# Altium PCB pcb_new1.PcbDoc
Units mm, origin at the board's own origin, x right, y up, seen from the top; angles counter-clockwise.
Board outline 81.51 x 54.69 mm, 2 copper layers (Top Layer, Bottom Layer); 60 components, 48 nets, 246 pads, 37 vias.
Unrouted connection lines stored in the file: 3.
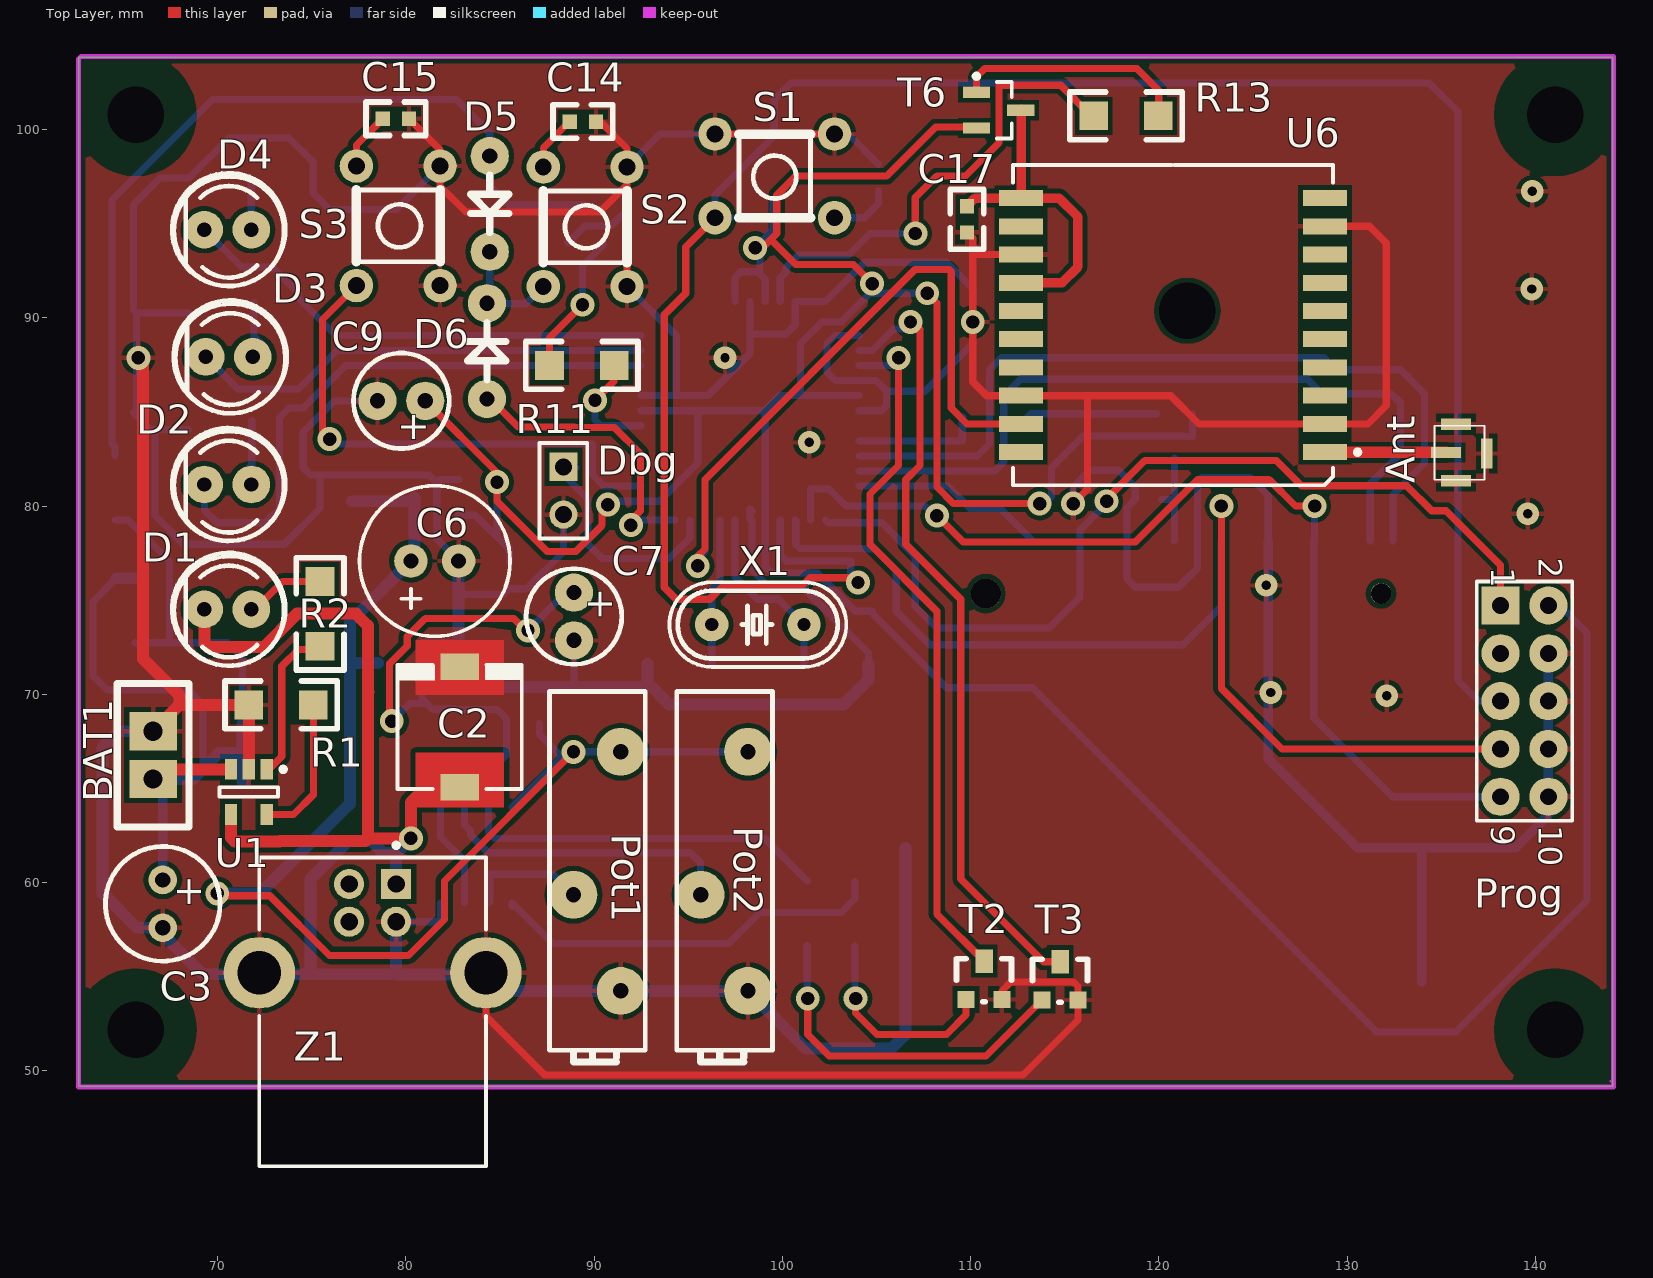
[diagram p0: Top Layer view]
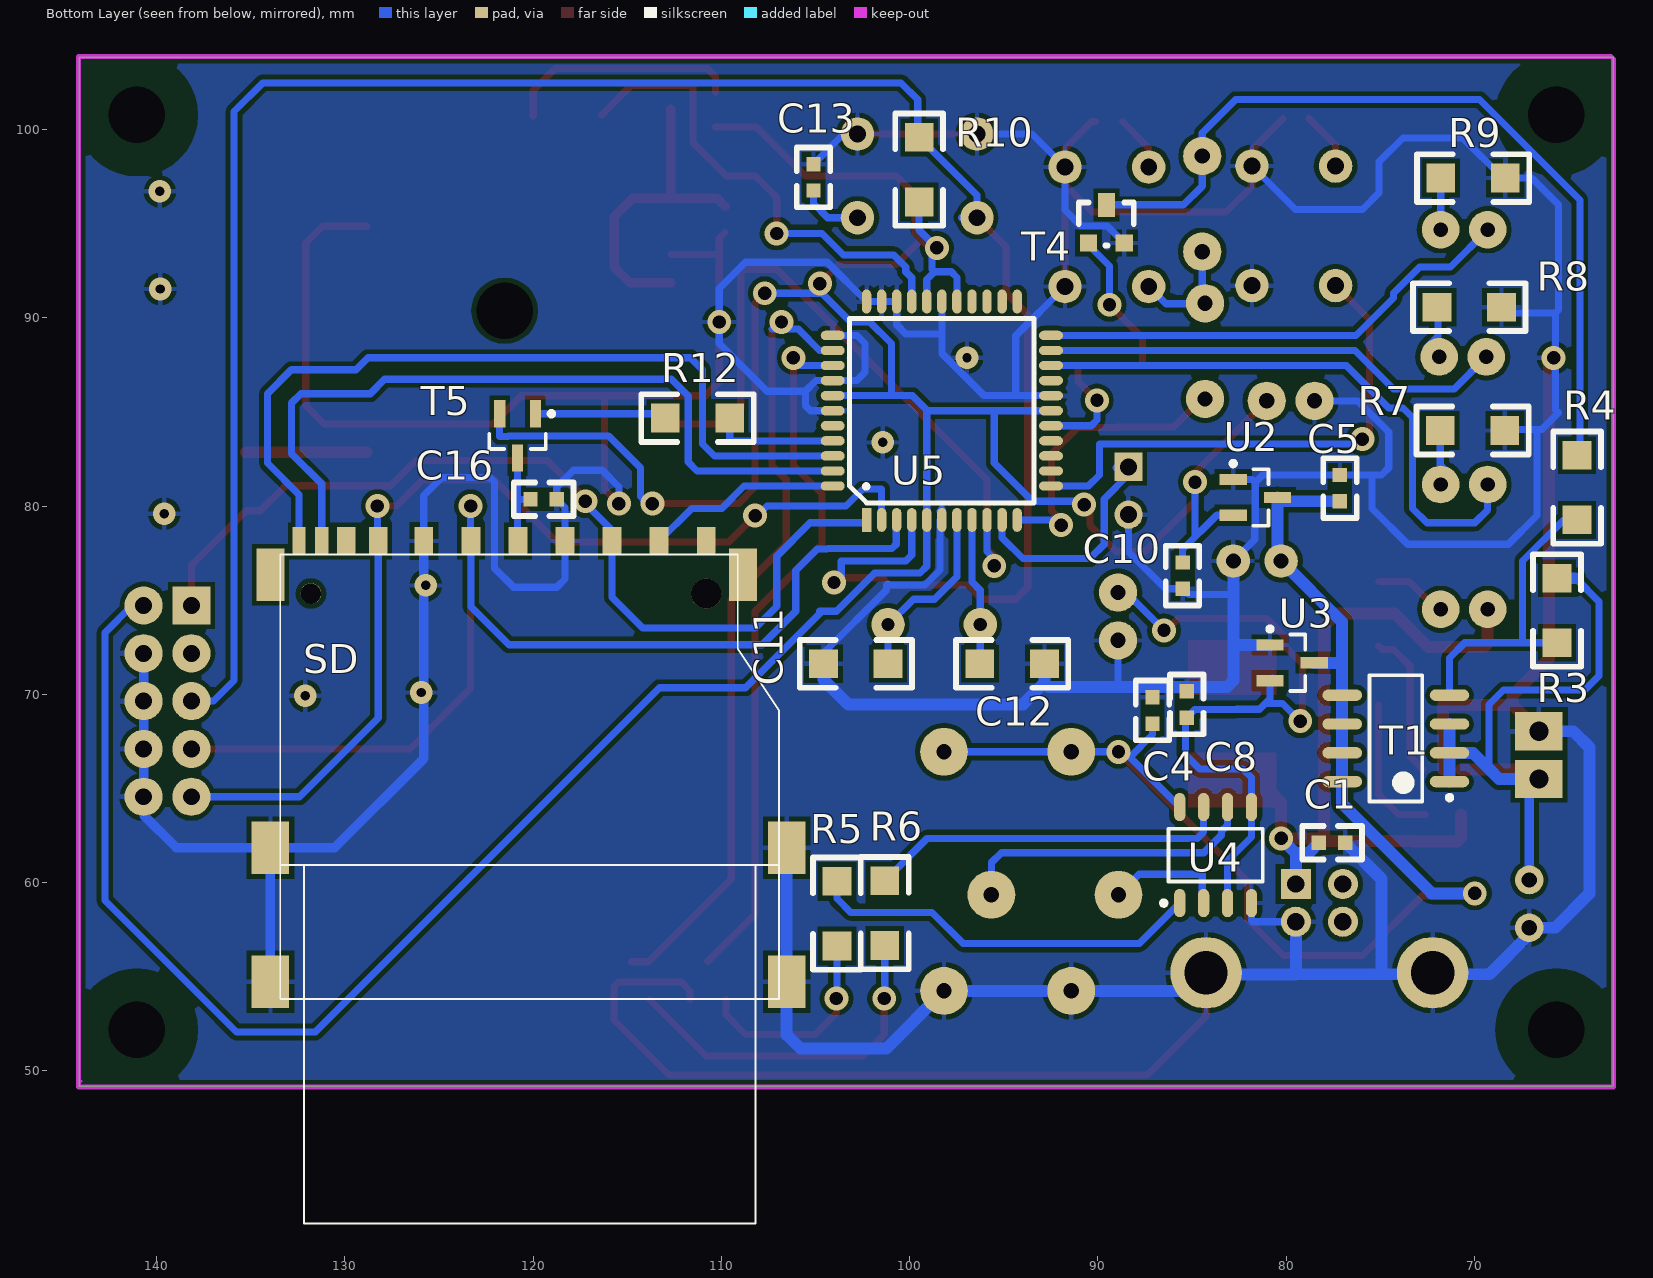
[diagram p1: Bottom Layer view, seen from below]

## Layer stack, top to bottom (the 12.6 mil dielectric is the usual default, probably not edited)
Top Layer: signal copper 0.0356
Dielectric: core 0.32, FR-4, Dk 4.8
Bottom Layer: signal copper 0.0356

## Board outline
62.611,103.861 62.611,49.174 144.12,49.174 144.12,103.861

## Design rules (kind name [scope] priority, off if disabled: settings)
Clearance [All] p1: gap=0.254
PolygonConnect [All] p1: connectstyle=Relief reliefconductorwidth=0.254 reliefentries=4 polygonreliefangle="90 Angle"
RoutingVias [All] p1: holewidth=0.711 width=1.27 viastyle="Through Hole" minholewidth=0.711 minwidth=1.27 maxholewidth=0.711 maxwidth=1.27
SilkscreenOverComponentPads [All] p1: minsilkscreentomaskgap=0.254
SolderMaskExpansion [All] p1: expansion=0.102
Width [All] p1: maxlimit=0.762 minlimit=0.254 preferedwidth=0.508 toplayer_prefwidth=0.381 minimp=50.000000 maximp=50.000000 favimp=50.000000
27 further rules are at their usual default settings.

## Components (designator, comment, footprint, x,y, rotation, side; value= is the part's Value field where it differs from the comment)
Ant "Antenna" ipx 135.738,85.293 r90 top
BAT1 "BAT" jmp2 66.573,65.507 r0 top
C1 "100nF" 0603 78.257,62.128 r180 bottom
C2 "100uF" kondel_smd 85.115,70.79 r90 top
C3 "100uF" ce6 67.081,60.147 r270 top
C4 "100nF" 0603 87.097,68.453 r90 bottom
C5 "100nF" 0603 77.14,80.264 r90 bottom
C6 "100uF" "C el./2.5mm" 80.264,77.089 r0 top
C7 "100uF" ce5 88.925,75.413 r270 top
C8 "100nF" 0603 85.28,68.771 r90 bottom
C9 "100uF" ce5 81.026,85.598 r180 top
C10 "100nF" 0603 85.496,77.013 r270 bottom
C11 "33pF" 1206 101.143,71.628 r0 bottom
C12 "33pF" 1206 96.266,71.628 r180 bottom
C13 "100nF" 0603 105.105,96.774 r90 bottom
C14 "10nF" 0603 90.094,100.432 r180 top
C15 "10nF" 0603 80.162,100.584 r180 top
C16 "100nF" 0603 120.142,80.366 r180 bottom
C17 "100nF" 0603 109.804,94.539 r90 top
D1 "LED0" "LED 3 MM" 69.291,74.524 r0 top
D2 "LED0" "LED 3 MM" 69.291,81.153 r0 top
D3 "LED0" "LED 3 MM" 69.367,87.935 r0 top
D4 "LED0" "LED 3 MM" 69.291,94.691 r0 top
D5 "D" D2 84.455,98.603 r270 top (schematic designator D6)
D6 "D" D2 84.303,85.7 r90 top (schematic designator D7)
Dbg "Header 2" HDR1X2 88.367,82.093 r270 top
Pot1 "RPOT" heli 91.44,54.28 r180 top
Pot2 "RPOT" heli 98.196,54.28 r180 top
Prog "AVR_PROG" hdr2x5 138.151,74.727 r270 top
R1 "*" 1206 71.653,69.444 r0 top
R2 "470R" 1206 75.438,75.997 r270 top
R3 "1k" 1206 65.608,76.175 r270 bottom
R4 "220R" 1206 64.541,79.273 r90 bottom
R5 "1k" 1206 103.861,60.071 r270 bottom
R6 "1k" 1206 101.321,60.096 r270 bottom
R7 "470R" 1206 71.806,84.023 r180 bottom
R8 "470R" 1206 68.555,90.576 r0 bottom
R9 "470R" 1206 68.351,97.434 r0 bottom
R10 "47k" 1206 99.492,96.164 r90 bottom
R11 "220R" 1206 87.63,87.478 r0 top
R12 "1k" 1206 109.55,84.684 r0 bottom
R13 "1k" 1206 116.535,100.736 r0 top
S1 "MSWITCH" MSWITCH 102.768,99.771 r270 top
S2 "MSWITCH" MSWITCH 87.3,98.019 r0 top
S3 "MSWITCH" MSWITCH 77.368,98.069 r0 top
SD "SD-MMC" SD-MMC 132.182,60.909 r180 bottom
T1 "IRF7416 PMOS" IRF7416 74.168,67.691 r0 bottom
T2 "BC548B" "sot-23 rk" 109.753,53.797 r0 top
T3 "BC548B" "sot-23 rk" 113.792,53.772 r0 top
T4 "" "sot-23 rk" 90.5,93.98 r180 bottom
T5 "BC857 {PNP}" SOT95P240-3M 120.828,83.738 r270 bottom
T6 "BC857 {PNP}" SOT95P240-3M 111.481,101.041 r0 top
U1 "MCP73831" sot23-5an 71.653,64.821 r270 top
U2 "MCP1700" SOT95P240-3M 81.636,80.467 r180 bottom
U3 "MCP1700" SOT95P240-3M 79.68,71.679 r180 bottom
U4 "LM358" SOIC127P600-8BL 83.744,61.468 r90 bottom
U5 "ATmega32L-8AC" TQFP44-08 102.286,79.273 r90 bottom
U6 "Odbiornik GPS" GPS 118.059,100.33 r180 top
X1 "X" X 101.143,73.711 r180 top
Z1 "USB_con" USB_B 78.232,58.928 r270 top

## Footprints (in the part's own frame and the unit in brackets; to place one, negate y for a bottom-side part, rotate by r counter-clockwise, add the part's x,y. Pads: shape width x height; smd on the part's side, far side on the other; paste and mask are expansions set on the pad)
0603 [mil]
  rect 30x30 smd: 1(0,0) 2(55,0)
  silkscreen extent -35,-35 90,35
1206 [mil]
  rect 60x60 smd: 1(0,0) 2(135,0)
  silkscreen extent -50,-50 185,50
"C el./2.5mm" [mil]
  round 70 hole 31.5: 1(0,0) 2(100,0)
  silkscreen extent -107,-157 207,157
ce5 [mil]
  round 80 hole 32: 1(0,0) 2(100,0)
  silkscreen extent -50,-100 150,100
ce6 [mil]
  round 60 hole 32: 1(0,0) 2(100,0)
  silkscreen extent -70,-120 170,120
D2 [mil]
  round 80 hole 32: 1(0,0) 2(200,0)
  silkscreen extent 40,-40 160,40
GPS [mm]
  round 0 hole 3 unplated: 0(-3.457,9.948)
  rect 2.35x0.85 smd: 1(5.38,3.96) 2(5.38,5.46) 3(5.38,6.96) 4(5.38,8.46) 5(5.38,9.96) 6(5.38,11.46) 7(5.38,12.96) 8(5.38,14.46) 9(5.38,15.96) 10(5.38,17.46) 11(-10.77,17.46) 12(-10.77,15.96) 13(-10.77,14.46) 14(-10.77,12.96) 15(-10.77,11.46) 16(-10.77,9.96) 17(-10.77,8.46) 18(-10.77,6.96) 19(-10.77,5.46) 20(-10.77,3.96)
  silkscreen extent -12.62,2.21 5.81,19.21
HDR1X2 [mm] "Connector; Header; 2 Position"
  rect 1.5x1.5 hole 0.9: 1(0,0)
  round 1.5 hole 0.9: 2(2.54,0)
  silkscreen extent -1.27,-1.27 3.81,1.27
hdr2x5 [mil] "Connector; Header; 5x2 Position"
  rect 80x80 hole 35.43: 1(0,0)
  round 80 hole 35.43: 2(0,100) 3(100,0) 4(100,100) 5(200,0) 6(200,100) 7(300,0) 8(300,100) 9(400,0) 10(400,100)
  silkscreen extent -50,-50 450,150
heli [mil]
  round 100 hole 32: 1(1,1) 2(1,-499) 3(100,-200)
  silkscreen extent -50,-625 150,150
ipx [mm]
  rect 0.6x1.6 smd: 1(-2.438,0.483) 2(-3.937,-0.051) 2(-0.94,-0.051)
  rect 1.6x0.6 smd: 2(-2.489,-1.676)
  silkscreen extent -3.89,-1.55 -1.02,1.09
IRF7416 [mm]
  oval 2.1x0.6 smd: 1(-2.85,-0.74) 1(-2.85,0.79) 1(-2.85,2.32) 4(-2.85,-2.27) 5(2.85,-2.27) 5(2.85,-0.74) 5(2.85,0.79) 5(2.85,2.32)
  silkscreen extent -2.97,-3.32 1.4,3.38
jmp2 [mil]
  rect 100x80 hole 40: 1(0,0) 2(0,100)
  silkscreen extent -75,-100 75,200
kondel_smd [mm] "Precision Wire Wound Inductor, 2-Leads, Body 6,6x6,6mm, IPC Medium Density"
  rect 1.4x2.05 smd: 1(-5.715,2.261) 2(0.685,2.261)
  silkscreen extent -5.81,-1.04 0.79,5.56
"LED 3 MM" [mm]
  round 2 hole 0.762: 1(0,0) 2(2.5,0)
  silkscreen extent -1.7,-3 4.3,3
MSWITCH [mil]
  round 70 hole 35: 1(0,0) 1(0,-250) 2(175,0) 2(175,-250)
  silkscreen extent 0,-200 175,-50
SD-MMC [mm]
  rect 2x2.8 smd: 0(-1.773,-6.165) 0(-1.773,0.947) 0(25.652,-6.165) 0(25.652,0.947)
  rect 1.5x2.8 smd: 0(-1.773,15.447) 0(23.327,15.447)
  round 1.1 hole 1.1: 0(0.377,14.447)
  round 1.6 hole 1.6: 0(21.377,14.447)
  rect 1x1.5 smd: 1(18.877,17.247) 2(16.377,17.247) 3(13.877,17.247) 4(11.377,17.247) 5(8.877,17.247) 6(6.377,17.247) 7(3.952,17.247) 8(2.252,17.247) 9(21.377,17.247)
  rect 0.7x1.5 smd: 10(0.952,17.247) 11(-0.248,17.247)
  silkscreen extent -1.25,-19 25.25,16.52
SOIC127P600-8BL [mm] "SOIC, 8-Leads, Body 4.9x3.9mm, Pitch 1.27mm, IPC High Density"
  oval 1.5x0.6 smd: 1(-2.55,1.905) 2(-2.55,0.635) 3(-2.55,-0.635) 4(-2.55,-1.905) 5(2.55,-1.905) 6(2.55,-0.635) 7(2.55,0.635) 8(2.55,1.905)
  silkscreen extent -2.67,-2.5 1.4,2.88, body extent -2,-2.5 2,2.5, height 2.59
sot23-5an [mm] "SOT23, 5-Leads, Body 2.9x1.6mm, Pitch 0.95mm, Lead Span 2.8mm, IPC Medium Density"
  rect 1.1x0.65 smd: 1(-1.2,0.95) 2(-1.2,0) 3(-1.2,-0.95) 4(1.2,-0.95) 5(1.2,0.95)
  silkscreen extent -1.32,-1.55 0.25,1.95, body extent -0.9,-1.55 0.9,1.55, height 1.45
SOT95P240-3M [mm] "SOT23, 3-Leads, Body 2.9x1.3mm, Pitch 0.95mm, Lead Span 2.4mm, IPC Low Density"
  rect 1.45x0.6 smd: 1(-1.175,0.95) 2(-1.175,-0.95) 3(1.175,0)
  silkscreen extent -1.3,-1.5 0.7,1.92, body extent -0.7,-1.5 0.7,1.5, height 1.14
"sot-23 rk" [mm]
  rect 0.914x0.914 smd: 1(1.905,0) 2(0,0)
  rect 0.914x1.27 smd: 3(0.965,2.032)
  silkscreen extent -0.51,-0.13 2.41,2.16
TQFP44-08 [mm] "TQFP44-08"
  rect 1.27x0.5 smd: 1(0,0)
  oval 1.27x0.5 smd: 2(0,-0.8) 3(0,-1.6) 4(0,-2.4) 5(0,-3.2) 6(0,-4) 7(0,-4.8) 8(0,-5.6) 9(0,-6.4) 10(0,-7.2) 11(0,-8) 23(11.6,-8) 24(11.6,-7.2) 25(11.6,-6.4) 26(11.6,-5.6) 27(11.6,-4.8) 28(11.6,-4) 29(11.6,-3.2) 30(11.6,-2.4) 31(11.6,-1.6) 32(11.6,-0.8) 33(11.6,0)
  oval 0.5x1.27 smd: 12(1.8,-9.8) 13(2.6,-9.8) 14(3.4,-9.8) 15(4.2,-9.8) 16(5,-9.8) 17(5.8,-9.8) 18(6.6,-9.8) 19(7.4,-9.8) 20(8.2,-9.8) 21(9,-9.8) 22(9.8,-9.8) 34(9.8,1.8) 35(9,1.8) 36(8.2,1.8) 37(7.4,1.8) 38(6.6,1.8) 39(5.8,1.8) 40(5,1.8) 41(4.2,1.8) 42(3.4,1.8) 43(2.6,1.8) 44(1.8,1.8)
  silkscreen extent 0.9,-8.9 10.7,0.9
USB_B [mm] "Connector; USB1.1, Type B, Thru-Hole; 4 Position; Right Angle"
  rect 1.6x1.6 hole 0.92: 1(-1,1.25)
  round 1.6 hole 0.92: 2(-1,-1.25) 3(1,-1.25) 4(1,1.25)
  round 3.8 hole 2.3: 5(3.71,6.02) 5(3.71,-6.02)
  silkscreen extent -3.18,-6.02 13.99,6.02, body extent -2.41,-6.02 13.99,6.02, height 11.1
X [mil]
  round 70 hole 27.56: 1(0,0) 2(192.91,0)
  silkscreen extent -88,-89 281,89

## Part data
Ant: "Generic Antenna"
BAT1: "Voltage Source - bateria i zasilacz"
C1 C4 C5 C8 C10 C11 C12 C13 C14 C15 C16 C17: library part CAP, "Condenstor"
C2 C3 C6 C7 C9: library part CAP2, "kONDENSATOR ELEKTROLITYCZNY"
D1 D2 D3 D4: "dioda elektroluminescencyjna LED"
D5 D6: "Dioda"
Dbg: "Header, 2-Pin"
Pot1 Pot2: "Potencjometr"
R1 R2 R3 R4 R5 R6 R7 R8 R9 R10 R11 R12 R13: library part RES, "Rezystor"
T2 T3: "Tranzystor NPN"
T4: library part BC547B, "Tranzystor NPN"
U4: "Low-Noise JFET-Input Operational Amplifiers"
U5: "8-Bit AVR Microcontroller with 32K Bytes of In-System Programmable Flash Memory"
X1: "Kwarc"

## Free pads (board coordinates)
  round 0 hole 3 unplated: 0(65.646,100.787) 1(141.046,100.787) 2(141.046,52.187) 3(65.646,52.187)

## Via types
v1: diameter 1.27, hole 0.711, Top Layer to Bottom Layer, 29 vias
v2: diameter 1.2, hole 0.5, Top Layer to Bottom Layer, 8 vias

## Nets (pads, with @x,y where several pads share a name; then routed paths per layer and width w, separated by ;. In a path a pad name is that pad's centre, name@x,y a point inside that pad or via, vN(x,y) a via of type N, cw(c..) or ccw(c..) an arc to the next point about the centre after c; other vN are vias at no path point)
CD: SD.10 U5.43 | length 41.3
  Bottom Layer w0.381: U5.43 111.29,81.873 111.76,82.343 111.76,85.852 112.649,86.741 127.889,86.741 128.651,85.979 132.334,85.979 132.842,85.471 132.842,82.804 131.23,81.192 SD.10
COMP1: T2.3 U5.36 | length 37.7
  Top Layer w0.381: v1@106.426,87.884 v1(106.172,87.884) 106.172,82.169 104.648,80.645 104.648,77.978 108.204,74.422 108.204,58.344 T2.3
  Bottom Layer w0.381: U5.36 105.761,87.473 v1(106.172,87.884)
COMP2: T3.3 U5.35 | length 41.5
  Top Layer w0.381: 107.315,89.408 107.315,82.169 106.553,81.407 106.553,77.978 109.474,75.057 109.474,60.198 113.868,55.804 T3.3
  Bottom Layer w0.381: U5.35 104.783,88.273 105.918,89.408 107.315,89.408
  other v1: 106.807,89.789
DEBUG: Dbg.1 U5.10 | length 12.5
  Bottom Layer w0.381: Dbg.1@89.027,82.042 88.417,82.042 Dbg.1 88.367,81.686 89.662,80.391 89.662,77.978 90.424,77.216 93.98,77.216 95.086,78.322 U5.10
GND: Ant.2 BAT1.2 C1.2 C2.2 C3.2 C4.2 C5.2 C6.2 C7.2 C8.2 C9.2 C10.2 C11.2 C12.2 C13.2 C14.1 C15.1 C16.2 C17.1 Dbg.2 Pot1.1 Pot2.1 Prog.4 Prog.6 Prog.8 Prog.10 R1.1 R7.2 R8.1 R9.1 S1.1 S2.2 S3.2 SD.0@106.53,54.744 SD.0@106.53,61.856 SD.0@133.955,54.744 SD.0@133.955,61.856 SD.3 SD.6 T2.1 T3.1 T4.1 U1.2 U2.1 U3.1 U4.4 U5.6 U5.18 U5.28 U5.31 U5.32 U5.33 U5.34 U5.37 U5.39 U6.3 U6.8 U6.12 U6.19 Z1.4 Z1.5 | length 509.7
  Top Layer w0.381: C15.1 81.813,98.933 81.813,98.069 81.813,97.003 83.185,95.631 90.297,95.631 91.745,97.079 S2.2@91.745,98.019 ; Z1.5@84.252,55.218 84.252,52.908 87.376,49.784 112.776,49.784 115.697,52.705 T3.1 115.697,54.483 115.456,54.724 112.128,54.724 111.658,54.254 T2.1 ; C14.1 90.322,100.432 91.745,99.009 S2.2@91.745,98.019 ; S2.2@91.745,91.669 S2.2@91.745,98.019 ; S1.1@96.418,99.771 S1.1@102.768,99.771 ; C17.1 110.109,94.234 110.109,93.345 ; U6.3 110.134,93.37 110.109,93.345 ; v1@115.57,80.013 115.57,80.264 116.205,80.899 116.205,85.743 116.332,85.87 ; U6.19 131.19,94.87 132.08,93.98 132.08,85.344 131.106,84.37 U6.12 122.132,84.37 120.632,85.87 116.332,85.87 ; 110.109,93.345 v1(110.109,89.789) 110.109,86.614 110.853,85.87 U6.8 116.332,85.87
  Top Layer w0.635: v1(65.786,87.884) 66.04,87.63 66.04,71.882 67.97,69.952 67.97,69.444 ; BAT1.2 67.97,69.444 ; U1.2 R1.1 67.97,69.444
  Bottom Layer w0.381: R9.1@68.29,97.409 ccw(c68.29,97.496) R9.1 ; R7.2@68.453,84.074 66.675,84.074 ; R8.1@68.478,90.272 65.684,90.272 ; C9.2 76.2,85.598 74.549,83.947 74.549,82.042 74.93,81.661 75.438,81.661 ; Z1.4 81.772,57.928 81.839,57.995 U4.4 ; S3.2@81.813,98.069 79.502,95.758 75.946,95.758 75.057,96.647 75.057,98.298 73.787,99.568 70.612,99.568 68.478,97.434 R9.1 ; 82.804,75.311 85.192,75.311 C10.2 86.411,75.616 88.367,77.572 Dbg.2 ; C6.2 81.661,78.232 81.661,78.994 81.641,79.014 81.641,81.26 ; U2.1 81.798,81.417 81.641,81.26 ; T4.1 89.51,94.894 90.907,94.894 91.745,95.733 91.745,98.019 93.497,99.771 S1.1@96.418,99.771 ; 88.773,70.409 88.925,70.561 C7.2 ; Pot1.1 Pot2.1 ; S2.2@91.745,91.669 94.361,89.052 94.361,85.873 ; U5.18 94.361,85.873 ; U5.6 98.286,79.841 U5.6@98.391,79.735 ; U5.28 98.286,89.154 ; U5.6@98.391,79.273 98.391,76.606 99.178,75.819 101.219,75.819 101.219,75.562 104.572,72.21 C11.2 ; S1.1@102.768,99.771 103.505,99.771 C13.2 ; U5.39 105.266,85.073 105.537,85.344 105.537,86.106 ; U5.34 102.789,89.073 102.362,88.646 102.362,87.114 102.802,86.673 U5.37 104.97,86.673 105.537,86.106 ; v1(115.443,80.137) 115.443,81.026 116.332,81.915 117.856,81.915 118.745,81.026 C16.2 118.305,79.925 SD.3 118.305,76.132 118.745,75.692 121.031,75.692 122.047,76.708 122.047,81.28 122.301,81.534 124.841,81.534 125.805,80.57 SD.6 ; 65.684,90.272 65.532,90.424 65.532,96.012 66.954,97.434 R9.1 ; 65.684,90.272 65.684,87.884 65.684,85.115 65.532,84.963 66.421,84.074 66.675,84.074 ; 66.675,84.074 66.675,79.502 68.199,77.978 73.533,77.978 75.438,79.883 75.438,81.661 ; 75.438,81.661 C5.2 81.24,81.661 81.641,81.26 ; 94.361,85.873 96.033,85.873 98.286,88.126 98.286,89.154 ; 98.286,89.154 100.203,89.154 100.686,89.637 U5.31 U5.32 U5.33 104.376,92.964 108.712,92.964 110.109,91.567 v1(110.109,89.789) 110.109,88.646 107.569,86.106 105.537,86.106
  Bottom Layer w0.508: SD.6 125.805,66.6 130.549,61.856 SD.0@133.955,61.856 ; SD.0@133.955,54.744 SD.0@133.955,61.856 ; Prog.4 Prog.6 Prog.8 Prog.10 140.691,63.602 138.945,61.856 SD.0@133.955,61.856
  Bottom Layer w0.635: BAT1.2@65.684,68.047 BAT1.2 64.745,68.047 63.881,67.183 63.881,59.436 65.71,57.607 C3.2 67.081,57.252 69.195,55.138 74.93,55.138 ; v1@65.684,87.884 v1(65.786,87.884) ; C1.2 74.93,60.198 74.93,55.138 ; Z1.4 79.482,55.138 ; U3.1 82.789,72.629 ; C6.2 82.804,75.311 82.804,70.739 83.134,70.409 88.773,70.409 92.634,70.409 ; C12.2 92.837,70.612 93.98,69.469 103.251,69.469 104.572,70.79 C11.2 ; SD.0@106.53,61.856 106.53,54.744 106.53,51.92 105.791,51.181 101.244,51.181 Pot2.1 Pot1.1 85.016,54.254 84.152,55.118 79.502,55.118 79.482,55.138 ; 74.93,55.138 79.482,55.138
  other v2: 132.105,69.926 125.933,70.104 125.705,75.794 139.598,79.604 101.422,83.388 96.952,87.884 139.802,91.542 139.827,96.723
GPS_INFO: U5.9 U6.9 | length 35.6
  Top Layer w0.381: v1@95.504,77.216 95.504,77.343 95.885,77.724 95.885,81.407 107.061,92.583 108.839,92.583 108.966,92.456 108.966,85.217 109.813,84.37 U6.9
  Bottom Layer w0.381: v1@95.504,77.216 95.886,77.598 U5.9
  other v1: 95.504,76.835
LD1: D2.1 U5.20 | length 31.3
  Bottom Layer w0.381: D2.1@69.291,81.356 D2.1 69.291,79.807 69.977,79.121 72.517,79.121 73.279,79.883 73.279,84.709 73.787,85.217 74.549,85.217 76.805,87.473 U5.20
LD2: D3.1 U5.21 | length 24.7
  Bottom Layer w0.381: D3.1 71.069,86.233 74.295,86.233 76.335,88.273 U5.21
LD3: D4.1 U5.22 | length 25.7
  Bottom Layer w0.381: D4.1 71.272,92.71 72.898,92.71 74.295,91.313 74.295,91.059 76.281,89.073 U5.22
MISO: Prog.9 SD.7 U5.2 | length 54.5
  Top Layer w0.381: v1(108.204,79.502) 109.601,78.105 118.745,78.105 122.047,81.407 125.857,81.407 127.254,80.01 v1(128.27,80.01)
  Bottom Layer w0.381: U5.2 101.486,80.912 102.476,80.912 103.378,80.01 107.569,80.01 108.077,79.502 v1(108.204,79.502) ; v1(128.27,80.01) 128.27,78.197 SD.7 128.23,68.747 132.41,64.567 Prog.9
MOSI: Prog.1 SD.2 U5.1 | length 50.2
  Top Layer w0.381: v1@117.094,80.01 117.094,80.264 119.253,82.423 126.238,82.423 127.572,81.09 133.16,81.09 134.493,79.756 135.255,79.756 138.151,76.86 Prog.1
  Bottom Layer w0.381: U5.1 102.438,79.121 105.283,79.121 107.061,77.343 107.061,74.676 108.204,73.533 114.173,73.533 115.805,75.165 SD.2 ; SD.2@115.824,78.176 SD.2 ; v1@117.094,80.01 115.805,78.721 SD.2
  other v1: 117.221,80.264
NetAnt_1: Ant.1 U6.11 | length 6.4
  Top Layer w0.381: U6.11 U6.11@128.844,82.855
  Top Layer w0.61: U6.11@128.844,82.855 Ant.1
NetBAT1_1: BAT1.1 C3.1 T1.1 U1.3 | length 35.4
  Top Layer w0.508: BAT1.1 BAT1.1@67.081,64.999
  Top Layer w0.635: BAT1.1 67.088,66.021 U1.3
  Bottom Layer w0.381: 64.618,76.175 63.373,74.93 63.373,70.993 64.135,70.231 68.453,70.231 69.214,69.47 69.214,66.039
  Bottom Layer w0.508: BAT1.1@67.056,65.507 67.081,65.481 C3.1
  Bottom Layer w0.635: 64.618,76.175 65.608,76.175 ; BAT1.1 67.056,65.507 68.682,65.507 69.214,66.039 70.076,66.901 T1.1@71.318,66.901 ; T1.1@71.318,65.371 T1.1@71.318,66.901 ; T1.1@71.318,68.431 T1.1@71.318,66.901
NetC1_1: C1.1 C2.1 D1.1 U1.4 Z1.1 | length 42.5
  Top Layer w0.635: D1.1 69.291,72.695 69.469,72.517 72.438,72.517 74.216,74.295 77.343,74.295 77.978,73.66 77.978,70.104 ; 70.703,62.931 U1.4 70.703,62.393 70.902,62.194 73.291,62.194 73.314,62.217 77.864,62.217 77.978,62.332 ; 78.003,70.129 77.978,70.104 ; 81.534,65.532 80.264,64.262 v1(80.264,62.357) 78.003,62.357 77.978,62.332 ; 77.978,62.332 77.978,70.104
  Bottom Layer w0.635: C1.1 78.811,61.575 79.482,61.575 ; Z1.1 79.482,61.575 ; v1(80.264,62.357) 79.482,61.575
NetC11_1: C11.1 U5.7 X1.1 | length 9.8
  Bottom Layer w0.381: U5.7 97.486,76.25 98.679,75.057 99.797,75.057 X1.1 C11.1
NetC12_1: C12.1 U5.8 X1.2 | length 7.8
  Bottom Layer w0.381: C12.1 96.243,71.651 X1.2 96.243,75.542 96.686,75.985 U5.8
NetC14_2: C14.2 D5.2 D6.2 S2.1 | length 9
  Top Layer w0.381: S2.1@87.3,98.019 87.3,99.035 C14.2
  Bottom Layer w0.381: D5.2 84.455,90.805 84.506,90.754 86.385,90.754 S2.1@87.3,91.669
NetC16_1: C16.1 SD.4 T5.3 | length 5.1
  Bottom Layer w0.381: C16.1 120.802,80.366 120.828,80.391 ; SD.4 120.828,78.179 120.828,80.391 ; T5.3@120.828,82.569 120.828,80.391
NetC17_2: C17.2 T6.3 U6.1 U6.4 | length 17.2
  Top Layer w0.508: C17.2 110.239,96.37 U6.1 ; U6.4 114.857,91.87 115.697,92.71 115.697,95.377 114.704,96.37 U6.1 ; T6.3@112.681,101.092 112.681,96.373 U6.1
NetD1_2: D1.2 R2.1 | length 3.9
  Top Layer w0.381: D1.2 71.984,74.524 73.457,75.997 R2.1@75.082,75.997
NetD2_2: D2.2 R7.1 | length 3
  Bottom Layer w0.381: D2.2@71.382,81.765 71.806,82.189 R7.1@71.806,84.557
NetD3_2: D3.2 R8.2 | length 4.1
  Bottom Layer w0.381: D3.2@71.867,87.401 72.105,87.401 72.568,87.864 72.568,88.39 71.933,89.025 R8.2@71.933,90.805
NetD4_2: D4.2 R9.2 | length 2.4
  Bottom Layer w0.381: R9.2@71.78,97.079 71.78,94.702 D4.2
NetPot1_3: Pot1.3 U4.2 | length 6.5
  Bottom Layer w0.381: U4.2 84.455,58.994 84.455,60.452 87.808,60.452 Pot1.3
NetPot2_3: Pot2.3 U4.6 | length 16.2
  Bottom Layer w0.381: U4.6 83.109,63.068 83.439,62.738 83.439,62.526 84.37,61.595 95.123,61.595 95.656,61.062 Pot2.3
NetR1_2: R1.2 U1.5 | length 7.7
  Top Layer w0.381: U1.5 74.035,63.621 75.082,64.668 R1.2
NetR2_2: R2.2 U1.1 | length 7.9
  Top Layer w0.381: U1.1@72.728,66.021 73.406,66.699 73.406,71.501 74.295,72.39 74.905,72.39 R2.2@75.082,72.568
NetR3_2: R3.2 R4.1 T1.4 | length 16.5
  Bottom Layer w0.381: R4.1 65.253,79.273 67.437,77.089 67.437,75.311 ; R3.2 67.564,72.746 ; 67.437,75.565 67.437,75.311 ; T1.4 71.318,71.938 70.51,72.746 67.564,72.746 ; 67.437,75.311 67.437,72.873 67.564,72.746
NetR5_1: R5.1 U4.1 | length 21.2
  Bottom Layer w0.381: U4.1@85.649,58.75 U4.1 87.798,56.769 97.155,56.769 98.806,58.42 103.124,58.42 103.861,59.157 R5.1
NetR5_2: R5.2 T2.2 | length 11.2
  Top Layer w0.381: v1(103.886,53.848) 103.886,53.086 105.029,51.943 108.712,51.943 109.753,52.984 T2.2
  Bottom Layer w0.381: R5.2 103.861,53.873 v1(103.886,53.848)
NetR6_1: R6.1 U4.7 | length 19.3
  Bottom Layer w0.381: U4.7 84.379,62.687 84.709,62.357 99.06,62.357 R6.1
NetR6_2: R6.2 T3.2 | length 19.1
  Top Layer w0.381: v1(101.346,53.848) 101.346,51.943 102.489,50.8 110.82,50.8 T3.2
  Bottom Layer w0.381: R6.2 101.321,53.746 101.346,53.721 v1(101.346,53.848)
NetR11_1: R11.1 T4.2 | length 7.7
  Top Layer w0.381: R11.1 87.63,88.951 v1(89.383,90.703)
  Bottom Layer w0.381: v1(89.383,90.703) 89.383,92.761 90.5,93.878 T4.2
NetR11_2: R11.2 U5.16 | length 5.9
  Top Layer w0.381: v1(90.043,85.623) 91.059,86.639 R11.2
  Bottom Layer w0.381: v1(90.043,85.623) 90.043,84.582 90.352,84.273 U5.16
NetR12_2: R12.2 T5.1 | length 7
  Bottom Layer w0.381: R12.2 113.209,84.913 T5.1
NetR13_2: R13.2 T6.1 | length 12.5
  Top Layer w0.381: T6.1 110.306,102.813 110.744,103.251 118.821,103.251 119.99,102.083 R13.2@119.99,100.736
PC: R12.1 U5.41 | length 6.8
  Bottom Layer w0.381: U5.41 104.095,83.464 109.55,83.464 R12.1 R12.1@109.601,84.734
PG: R13.1 U5.30 | length 25.7
  Top Layer w0.381: v1(107.061,94.488) 107.061,96.393 108.204,97.536 109.728,97.536 111.506,99.314 111.506,102.362 114.783,102.362 R13.1@116.357,100.787
  Bottom Layer w0.381: U5.30 99.886,92.139 100.203,92.456 100.203,92.71 100.838,93.345 103.505,93.345 104.648,94.488 v1(107.061,94.488)
PWR: D5.1 R4.2 T4.3 | length 44.9
  Bottom Layer w0.381: R4.2 64.541,83.16 64.389,83.312 64.389,96.266 69.723,101.6 82.677,101.6 84.455,99.822 D5.1 84.455,97.003 85.446,96.012 T4.3
REF: C7.1 C8.1 U3.2 U4.3 U4.5 | length 36.7
  Top Layer w0.381: v1(79.248,68.58) 79.121,68.707 79.121,71.628 80.073,72.581 80.073,73.082 81.032,74.041 85.725,74.041 86.36,73.406 v1(86.487,73.406)
  Bottom Layer w0.381: v1(79.248,68.58) 80.184,69.516 81.106,69.516 ; U3.2@80.718,70.866 U3.2 80.855,69.767 81.106,69.516 ; U4.3 83.109,61.163 81.839,62.433 U4.5 81.839,65.583 82.296,66.04 84.582,66.04 85.344,66.802 85.344,68.707 84.849,69.202 82.634,69.202 82.622,69.215 81.407,69.215 81.106,69.516 ; v1(86.487,73.406) 88.494,75.413 C7.1
RESET: C13.1 Prog.5 R10.2 S1.2 U5.4 | length 120.9
  Top Layer w0.381: S1.2@96.418,95.326 94.869,93.777 94.869,91.313 93.726,90.17 93.726,75.692 94.361,75.057 96.139,75.057 96.901,75.819 101.092,75.819 101.473,76.2 103.759,76.2 v1(104.013,75.946)
  Bottom Layer w0.381: S1.2@97.231,95.326 96.418,95.326 96.418,96.52 99.568,99.67 99.568,101.6 100.457,102.489 134.366,102.489 135.89,100.965 135.89,70.739 136.982,69.647 Prog.5 ; U5.4 99.886,77.406 100.203,77.089 103.632,77.089 103.632,76.327 v1(104.013,75.946) ; S1.2@102.768,95.326 104.343,95.326 105.105,96.088 C13.1
SCK: Prog.7 SD.5 U5.3 | length 59.4
  Top Layer w0.381: v1(123.317,80.01) 123.317,70.333 126.543,67.107 Prog.7
  Bottom Layer w0.381: U5.3 100.711,79.248 100.711,77.978 100.94,77.749 104.369,77.749 104.394,77.724 104.902,77.724 106.045,76.581 106.045,74.422 107.823,72.644 121.285,72.644 123.305,74.664 SD.5 123.317,78.169 v1(123.317,80.01)
SS: SD.1 U5.44 | length 10.4
  Bottom Layer w0.381: U5.44 108.792,81.073 109.982,79.883 111.578,79.883 SD.1
SW1: D6.1 U5.11 | length 15.3
  Top Layer w0.381: D6.1@84.506,85.674 85.979,84.201 88.943,84.201 88.955,84.188 91.072,84.188 92.456,82.804 92.456,79.756 91.948,79.248 v1(91.948,78.994)
  Bottom Layer w0.381: v1@92.1,79.273 U5.11
SW2: C15.2 S3.1 U5.12 | length 30.8
  Top Layer w0.381: v1@75.565,83.693 75.565,89.916 S3.1@77.368,91.719 ; S3.1@77.368,98.069 77.368,99.187 C15.2
  Bottom Layer w0.381: v1@75.565,83.693 75.946,83.312 89.916,83.312 89.916,81.661 90.504,81.073 U5.12
  other v1: 75.946,83.566
VBAT: C4.1 C5.1 C6.1 Pot1.2 Pot2.2 T1.5 U2.3 U3.3 U4.8 | length 73.8
  Top Layer w0.381: v1(69.977,59.436) 69.977,59.309 72.771,59.309 75.946,56.134 80.137,56.134 82.042,58.039 82.042,60.096 v1(88.9,66.954)
  Bottom Layer w0.381: U4.8 88.297,66.667 ; C4.1 87.097,67.867 88.297,66.667 ; 88.297,66.744 88.297,66.667 ; Pot2.2 Pot1.2 v1(88.9,66.954) 88.585,66.954 88.297,66.667
  Bottom Layer w0.635: v1(69.977,59.436) 72.263,59.436 77.018,64.191 77.018,65.371 77.018,66.901 77.018,68.431 77.018,69.961 77.018,71.628 ; C5.1 80.257,80.264 U2.3 80.461,77.286 C6.1 77.018,73.843 77.018,71.628 ; U3.3 77.069,71.679 77.018,71.628
VCC: C9.1 C10.1 Prog.2 R10.1 T5.2 T6.2 U2.2 U5.5 U5.17 U5.27 U5.29 U5.38 | length 191
  Top Layer w0.381: C9.1 v1@84.836,81.788 ; v1(84.836,81.28) 84.836,80.264 87.503,77.597 89.027,77.597 90.424,78.994 v1@90.424,79.625 ; v1@98.806,93.599 99.377,94.17 ; v1(104.768,91.828) 103.759,92.837 100.711,92.837 99.377,94.17 ; 108.207,90.802 108.207,81.026 109.096,80.137 v1(113.665,80.137) ; T6.2@110.331,100.142 108.143,100.142 105.537,97.536 100.711,97.536 99.695,96.52 99.695,94.488 99.377,94.17
  Bottom Layer w0.381: U2.2 83.678,79.517 85.496,77.699 C10.1 ; 84.836,78.359 v1(84.836,81.28) ; v1@91.059,80.264 93.472,80.264 95.504,82.296 95.504,85.073 ; U5.17 95.504,85.073 ; U5.27 97.486,92.152 97.79,92.456 98.679,92.456 ; v1(98.552,93.726) 99.492,94.666 R10.1 ; v1@98.806,93.599 98.806,92.583 98.679,92.456 ; 99.043,85.073 95.504,85.073 ; U5.29 99.086,92.049 98.679,92.456 ; U5.38 100.965,85.873 ; v1@104.648,91.313 103.129,89.794 102.113,89.794 100.965,88.646 100.965,85.873 ; v1@104.655,91.828 v1(104.768,91.828) ; v1@104.768,91.313 v1(107.696,91.313) ; v1@114.046,80.264 114.3,80.518 114.3,82.042 115.996,83.738 121.312,83.738 ; 121.342,83.708 121.778,83.708 T5.2 ; Prog.2 141.3,74.727 142.748,73.279 142.748,59.055 135.763,52.07 131.572,52.07 113.284,70.358 108.712,70.358 106.426,72.644 104.775,74.295 104.775,74.422 103.886,74.422 101.854,76.454 99.441,76.454 99.086,76.809 U5.5 99.086,85.116 99.843,85.873 100.965,85.873
  other v1: 90.729,80.086
WP: SD.11 U5.42 | length 43.8
  Bottom Layer w0.381: U5.42 110.359,82.673 110.998,83.312 110.998,87.249 111.633,87.884 128.778,87.884 129.413,87.249 132.842,87.249 134.112,85.979 134.112,82.296 132.43,80.614 SD.11
pads on no net: Prog.3 R3.1 SD.0@108.855,76.356 SD.0@110.805,75.356 SD.0@131.805,75.356 SD.0@133.955,76.356 SD.8 SD.9 U5.13 U5.14 U5.15 U5.19 U5.23 U5.24 U5.25 U5.26 U5.40 U6.0 U6.2 U6.5 U6.6 U6.7 U6.10 U6.13 U6.14 U6.15 U6.16 U6.17 U6.18 U6.20 Z1.2 Z1.3

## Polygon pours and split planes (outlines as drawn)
GND on Bottom Layer "Bottom Layer-No Net" (solid, remove dead copper, pour order 1000): 62.589,103.712 62.589,49.356 62.462,49.229 62.589,49.356 143.996,49.356 143.996,103.712
GND on Top Layer "Bottom Layer-No Net" (solid, remove dead copper, pour order 1001): 62.611,103.759 62.611,49.403 143.891,49.403 144.145,49.149 144.145,103.886

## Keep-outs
Keep-Out Layer:
  lines w0.127: 143.993,49.454 144.145,49.454
  lines w0.254: 62.611,49.149 144.145,49.149 144.145,103.886 62.738,103.886 62.611,103.759 62.611,49.149

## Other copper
Top Layer:
  rectangle net GND: 80.518,69.977 85.217,72.898
  rectangle net NetC1_1: 80.518,64.008 85.217,66.929

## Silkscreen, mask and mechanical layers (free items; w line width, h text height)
Top Solder:
  rectangle: 133.807,82.55 134.29,83.16
  rectangle: 134.29,82.55 136.068,83.16
  rectangle: 134.95,81.077 136.55,81.661
  rectangle: 137.008,82.067 137.617,83.668
  rectangle: 134.95,84.049 136.576,84.684
  rectangle: 80.543,64.059 85.166,66.929
  rectangle: 80.543,69.977 85.192,72.898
